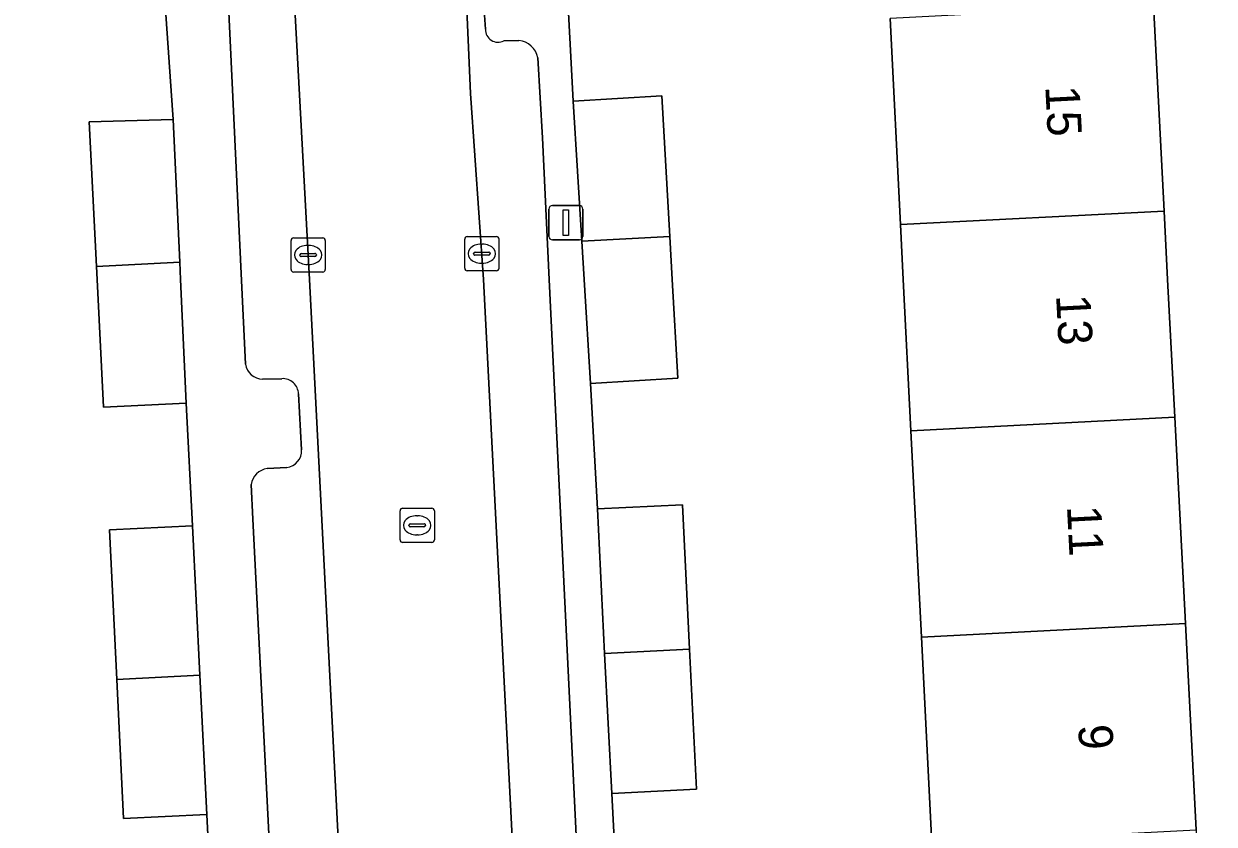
# Model space of a CAD drawing. Extents: x 161084 to 161928, y 385354 to 386522.
# Drawn here: x 161389.16 to 161423.93, y 385484.1 to 385507.46 of the extents above; entities that cross this region are included whole.
import ezdxf

# ---------------------------------------------------------------- set-up
doc = ezdxf.new("R2010")
doc.units = 0
for name, color, linetype in [('IMGEO_Erf', 7, 'Continuous'), ('IMGEO_Kolk', 7, 'Continuous'), ('IMGEO_Lichtmast', 7, 'Continuous'), ('IMGEO_Pand', 7, 'Continuous'), ('IMGEO_Pand_nummerreeks', 7, 'Continuous'), ('IMGEO_Parkeervlak_open', 7, 'Continuous'), ('IMGEO_Rijbaan_lokaal_open', 7, 'Continuous'), ('IMGEO_Rioolput', 7, 'Continuous'), ('IMGEO_Voetpad_open', 7, 'Continuous')]:
    doc.layers.add(name, color=color, linetype=linetype)

msp = doc.modelspace()

# ---------------------------------------------------------------- linework, layer by layer
at = {"layer": 'IMGEO_Erf'}
for points in [[(161425.182, 385526.476), (161421.216, 385526.254), (161421.535, 385520.062), (161421.846, 385514.041), (161422.156, 385508.02), (161422.467, 385501.999), (161422.57, 385500), (161422.777, 385495.978), (161423.088, 385489.958), (161423.399, 385483.937), (161423.709, 385477.916), (161424.02, 385471.895), (161424.33, 385465.874), (161424.65, 385459.679), (161419.05, 385459.388), (161419.359, 385453.441), (161419.358, 385452.841), (161429.459, 385453.441)], [(161394.687, 385480.676), (161394.502, 385484.379), (161392.074, 385484.26), (161391.874, 385488.326), (161391.66, 385492.693), (161394.088, 385492.812), (161393.902, 385496.387), (161391.492, 385496.269), (161391.304, 385500), (161391.285, 385500.382), (161391.073, 385504.601), (161393.525, 385504.669), (161393.274, 385508.311), (161390.803, 385508.201), (161390.615, 385512.436), (161390.43, 385516.594), (161392.9, 385516.704), (161392.682, 385520.324), (161390.265, 385520.214), (161390.069, 385524.53), (161383.553, 385524.217)], [(161405.014, 385508.902), (161405.206, 385505.204), (161407.797, 385505.358), (161408.03, 385501.253), (161408.101, 385500), (161408.264, 385497.118), (161405.708, 385496.967), (161405.915, 385493.3), (161408.396, 385493.424), (161408.607, 385489.21), (161408.812, 385485.12), (161406.331, 385484.996), (161406.529, 385481.207)], [(161415.683, 385483.538), (161415.378, 385489.56), (161415.072, 385495.58), (161414.848, 385500), (161414.767, 385501.601), (161414.461, 385507.622)]]:
    msp.add_lwpolyline(points, dxfattribs=at)
at = {"layer": 'IMGEO_Kolk'}
for p, q in [((161397.04, 385501.217), (161397.892, 385501.217)), ((161402.039, 385500.329), (161402.039, 385501.181)), ((161402.114, 385501.255), (161402.966, 385501.255)), ((161403.04, 385501.181), (161403.04, 385500.329)), ((161396.965, 385500.291), (161396.965, 385501.143)), ((161397.453, 385500.997), (161397.478, 385500.997)), ((161397.966, 385501.143), (161397.966, 385500.291)), ((161402.527, 385501.035), (161402.552, 385501.035)), ((161397.224, 385500.711), (161397.224, 385500.723)), ((161397.662, 385500.674), (161397.264, 385500.674)), ((161397.267, 385500.76), (161397.665, 385500.76)), ((161397.708, 385500.723), (161397.708, 385500.711)), ((161402.298, 385500.749), (161402.298, 385500.761)), ((161402.736, 385500.712), (161402.338, 385500.712)), ((161402.341, 385500.798), (161402.739, 385500.798)), ((161402.55, 385500.475), (161402.525, 385500.475)), ((161402.782, 385500.761), (161402.782, 385500.749)), ((161397.892, 385500.217), (161397.04, 385500.217)), ((161397.476, 385500.437), (161397.451, 385500.437)), ((161402.966, 385500.255), (161402.114, 385500.255))]:
    msp.add_line(p, q, dxfattribs=at)
for points in [[(161397.04, 385501.217), (161397.892, 385501.217)], [(161402.039, 385500.329), (161402.039, 385501.181)], [(161402.114, 385501.255), (161402.966, 385501.255)], [(161403.04, 385501.181), (161403.04, 385500.329)], [(161396.965, 385500.291), (161396.965, 385501.143)], [(161397.966, 385501.143), (161397.966, 385500.291)], [(161397.892, 385500.217), (161397.04, 385500.217)], [(161402.966, 385500.255), (161402.114, 385500.255)]]:
    msp.add_lwpolyline(points, dxfattribs=at)
for centre, radius, start, end in [((161397.042, 385501.141), 0.0765, 91.552, 178.448), ((161397.042, 385501.141), 0.0765, 91.552, 178.448), ((161397.89, 385501.141), 0.0765, 1.552, 88.448), ((161397.89, 385501.141), 0.0765, 1.552, 88.448), ((161402.116, 385501.179), 0.0765, 91.552, 178.448), ((161402.116, 385501.179), 0.0765, 91.552, 178.448), ((161402.964, 385501.179), 0.0765, 1.552, 88.448), ((161402.964, 385501.179), 0.0765, 1.552, 88.448), ((161397.264, 385500.72), 0.0403, 85.8775, 175.7526), ((161397.261, 385500.71), 0.0366, 178.938, 274.7102), ((161397.665, 385500.717), 0.043, 264.8664, 352.4533), ((161397.669, 385500.722), 0.0386, 1.7309, 96.639), ((161402.338, 385500.758), 0.0403, 85.8775, 175.7526), ((161402.335, 385500.748), 0.0366, 178.938, 274.7102), ((161402.739, 385500.755), 0.043, 264.8664, 352.4533), ((161402.743, 385500.76), 0.0386, 1.7309, 96.639), ((161397.042, 385500.293), 0.0765, 181.552, 268.448), ((161397.042, 385500.293), 0.0765, 181.552, 268.448), ((161397.89, 385500.293), 0.0765, 271.552, 358.448), ((161397.89, 385500.293), 0.0765, 271.552, 358.448), ((161402.116, 385500.331), 0.0765, 181.552, 268.448), ((161402.116, 385500.331), 0.0765, 181.552, 268.448), ((161402.964, 385500.331), 0.0765, 271.552, 358.448), ((161402.964, 385500.331), 0.0765, 271.552, 358.448)]:
    msp.add_arc(centre, radius, start, end, dxfattribs=at)
for centre, major_axis, ratio, start_param, end_param in [((161397.452, 385500.717), (-0.387, 0.002), 0.722429, 4.712389, 7.853982), ((161397.477, 385500.717), (-0.39, 0.002), 0.717154, 1.570796, 4.712389), ((161402.526, 385500.755), (-0.387, 0.002), 0.722429, 4.712389, 7.853982), ((161402.551, 385500.755), (-0.39, 0.002), 0.717154, 1.570796, 4.712389)]:
    msp.add_ellipse(centre, major_axis=major_axis, ratio=ratio, start_param=start_param, end_param=end_param, dxfattribs=at)
at = {"layer": 'IMGEO_Lichtmast'}
for p, q in [((161404.498, 385501.256), (161404.498, 385502.056)), ((161404.498, 385502.056), (161404.498, 385501.256)), ((161404.598, 385502.156), (161405.388, 385502.156)), ((161405.388, 385502.156), (161404.598, 385502.156)), ((161405.488, 385502.056), (161405.488, 385501.256)), ((161405.488, 385501.256), (161405.488, 385502.056)), ((161405.388, 385501.156), (161404.598, 385501.156)), ((161404.598, 385501.156), (161405.388, 385501.156))]:
    msp.add_line(p, q, dxfattribs=at)
msp.add_lwpolyline([(161404.918, 385502.031), (161405.068, 385502.031), (161405.068, 385501.281), (161404.918, 385501.281), (161404.918, 385502.031)], dxfattribs=at)
for centre, start, end in [((161404.598, 385502.056), 90, 180), ((161404.598, 385502.056), 90, 180), ((161405.388, 385502.056), 0, 90), ((161405.388, 385502.056), 360, 90), ((161404.598, 385501.256), 180, 270), ((161404.598, 385501.256), 180, 270), ((161405.388, 385501.256), 270, 0), ((161405.388, 385501.256), 270, 0)]:
    msp.add_arc(centre, 0.1, start, end, dxfattribs=at)
at = {"layer": 'IMGEO_Pand'}
for points in [[(161414.461, 385507.622), (161414.767, 385501.601), (161422.467, 385501.999), (161422.156, 385508.02)], [(161405.455, 385501.12), (161408.03, 385501.253), (161407.797, 385505.358), (161405.206, 385505.204)], [(161393.525, 385504.669), (161391.073, 385504.601), (161391.285, 385500.382), (161393.715, 385500.509)], [(161422.777, 385495.978), (161422.57, 385500), (161422.467, 385501.999), (161414.767, 385501.601), (161414.848, 385500), (161415.072, 385495.58)], [(161405.523, 385500), (161405.708, 385496.967), (161408.264, 385497.118), (161408.101, 385500), (161408.03, 385501.253), (161405.455, 385501.12)], [(161393.738, 385500), (161393.715, 385500.509), (161391.285, 385500.382), (161391.304, 385500), (161391.492, 385496.269), (161393.902, 385496.387)], [(161415.072, 385495.58), (161415.378, 385489.56), (161423.088, 385489.958), (161422.777, 385495.978)], [(161406.126, 385489.082), (161408.607, 385489.21), (161408.396, 385493.424), (161405.915, 385493.3)], [(161394.088, 385492.812), (161391.66, 385492.693), (161391.874, 385488.326), (161394.302, 385488.453)], [(161423.399, 385483.937), (161423.088, 385489.958), (161415.378, 385489.56), (161415.683, 385483.538)], [(161406.331, 385484.996), (161408.812, 385485.12), (161408.607, 385489.21), (161406.126, 385489.082)], [(161394.302, 385488.453), (161391.874, 385488.326), (161392.074, 385484.26), (161394.502, 385484.379)]]:
    msp.add_lwpolyline(points, close=True, dxfattribs=at)
at = {"layer": 'IMGEO_Parkeervlak_open'}
for points in [[(161401.636, 385518.603), (161402.21, 385505.43), (161402.592, 385500), (161404.623, 385460.419)], [(161399.561, 385459.962), (161397.507, 385500), (161396.523, 385518.161)], [(161394.8, 385515.226), (161395.52, 385499.972), (161395.632, 385497.526)], [(161402.646, 385507.306), (161402.532, 385508.956)], [(161403.622, 385506.975), (161403.18, 385506.972)], [(161405.911, 385471.462), (161405.819, 385472.957), (161404.502, 385500), (161404.307, 385504.135), (161404.172, 385506.471)], [(161396.131, 385497.087), (161396.696, 385497.104)], [(161397.183, 385496.66), (161397.275, 385495.025)], [(161396.843, 385494.508), (161396.267, 385494.481)], [(161395.804, 385494.019), (161395.854, 385493.005), (161396.855, 385473.285), (161396.915, 385472.082)]]:
    msp.add_lwpolyline(points, dxfattribs=at)
for centre, radius, start, end in [((161403.007, 385507.29), 0.362, 177.4648, 298.4859), ((161403.559, 385506.355), 0.624, 10.765, 84.233), ((161396.153, 385497.615), 0.528, 189.6724, 267.6476), ((161396.727, 385496.648), 0.457, 1.4522, 93.8367), ((161396.775, 385495.004), 0.501, 277.8318, 2.4047), ((161396.348, 385493.937), 0.55, 98.4403, 171.4358)]:
    msp.add_arc(centre, radius, start, end, dxfattribs=at)
at = {"layer": 'IMGEO_Rijbaan_lokaal_open'}
for points in [[(161404.623, 385460.419), (161402.592, 385500), (161402.21, 385505.43), (161401.636, 385518.603)], [(161396.523, 385518.161), (161397.507, 385500), (161399.561, 385459.962)]]:
    msp.add_lwpolyline(points, dxfattribs=at)
at = {"layer": 'IMGEO_Rioolput'}
for p, q in [((161400.151, 385492.398), (161400.151, 385493.25)), ((161400.226, 385493.324), (161401.078, 385493.324)), ((161401.152, 385493.25), (161401.152, 385492.398)), ((161400.41, 385492.818), (161400.41, 385492.83)), ((161400.453, 385492.867), (161400.851, 385492.867)), ((161400.639, 385493.104), (161400.664, 385493.104)), ((161400.894, 385492.83), (161400.894, 385492.818)), ((161400.848, 385492.781), (161400.45, 385492.781)), ((161400.662, 385492.544), (161400.637, 385492.544)), ((161401.078, 385492.324), (161400.226, 385492.324))]:
    msp.add_line(p, q, dxfattribs=at)
for points in [[(161400.151, 385492.398), (161400.151, 385493.25)], [(161400.226, 385493.324), (161401.078, 385493.324)], [(161401.152, 385493.25), (161401.152, 385492.398)], [(161401.078, 385492.324), (161400.226, 385492.324)]]:
    msp.add_lwpolyline(points, dxfattribs=at)
for centre, radius, start, end in [((161400.228, 385493.248), 0.0765, 91.552, 178.448), ((161400.228, 385493.248), 0.0765, 91.552, 178.448), ((161401.076, 385493.248), 0.0765, 1.552, 88.448), ((161401.076, 385493.248), 0.0765, 1.552, 88.448), ((161400.45, 385492.827), 0.0403, 85.8775, 175.7526), ((161400.447, 385492.817), 0.0366, 178.938, 274.7102), ((161400.851, 385492.824), 0.043, 264.8664, 352.4533), ((161400.855, 385492.829), 0.0386, 1.7309, 96.639), ((161400.228, 385492.4), 0.0765, 181.552, 268.448), ((161400.228, 385492.4), 0.0765, 181.552, 268.448), ((161401.076, 385492.4), 0.0765, 271.552, 358.448), ((161401.076, 385492.4), 0.0765, 271.552, 358.448)]:
    msp.add_arc(centre, radius, start, end, dxfattribs=at)
for centre, major_axis, ratio, start_param, end_param in [((161400.638, 385492.824), (-0.387, 0.002), 0.722429, 4.712389, 7.853982), ((161400.663, 385492.824), (-0.39, 0.002), 0.717154, 1.570796, 4.712389)]:
    msp.add_ellipse(centre, major_axis=major_axis, ratio=ratio, start_param=start_param, end_param=end_param, dxfattribs=at)
at = {"layer": 'IMGEO_Voetpad_open'}
for points in [[(161406.529, 385481.207), (161406.331, 385484.996), (161406.126, 385489.082), (161405.915, 385493.3), (161405.708, 385496.967), (161405.523, 385500), (161405.455, 385501.12), (161405.206, 385505.204), (161405.014, 385508.902), (161404.818, 385513.162), (161404.626, 385517.344), (161404.459, 385520.896), (161404.259, 385525.272), (161406.663, 385525.382), (161413.546, 385525.87), (161415.853, 385525.986), (161421.216, 385526.254), (161425.182, 385526.476)], [(161383.553, 385524.217), (161390.069, 385524.53), (161392.486, 385524.64), (161392.682, 385520.324), (161392.9, 385516.704), (161393.084, 385512.565), (161393.274, 385508.311), (161393.525, 385504.669), (161393.715, 385500.509), (161393.738, 385500), (161393.902, 385496.387), (161394.088, 385492.812), (161394.302, 385488.453), (161394.502, 385484.379), (161394.687, 385480.676)], [(161395.632, 385497.526), (161395.52, 385499.972), (161394.8, 385515.226)], [(161402.532, 385508.956), (161402.646, 385507.306)], [(161403.18, 385506.972), (161403.622, 385506.975)], [(161404.172, 385506.471), (161404.307, 385504.135), (161404.502, 385500), (161405.819, 385472.957), (161405.911, 385471.462)], [(161396.696, 385497.104), (161396.131, 385497.087)], [(161397.275, 385495.025), (161397.183, 385496.66)], [(161396.267, 385494.481), (161396.843, 385494.508)], [(161396.915, 385472.082), (161396.855, 385473.285), (161395.854, 385493.005), (161395.804, 385494.019)]]:
    msp.add_lwpolyline(points, dxfattribs=at)
for centre, radius, start, end in [((161403.007, 385507.29), 0.362, 177.4648, 298.4859), ((161403.559, 385506.355), 0.624, 10.765, 84.233), ((161396.153, 385497.615), 0.528, 189.6724, 267.6476), ((161396.727, 385496.648), 0.457, 1.4522, 93.8367), ((161396.775, 385495.004), 0.501, 277.8318, 2.4047), ((161396.348, 385493.937), 0.55, 98.4403, 171.4358)]:
    msp.add_arc(centre, radius, start, end, dxfattribs=at)

# ---------------------------------------------------------------- texts
at = {"layer": 'IMGEO_Pand_nummerreeks'}
for s, rotation, p in [('15', 272.9528, (161418.995, 385505.637)), ('13', 272.953, (161419.31, 385499.542)), ('11', 272.953, (161419.628, 385493.382)), ('9', 272.953, (161419.956, 385486.99))]:
    msp.add_text(s, height=1, rotation=rotation, dxfattribs=at).set_placement(p)

doc.saveas('drawing.dxf')
